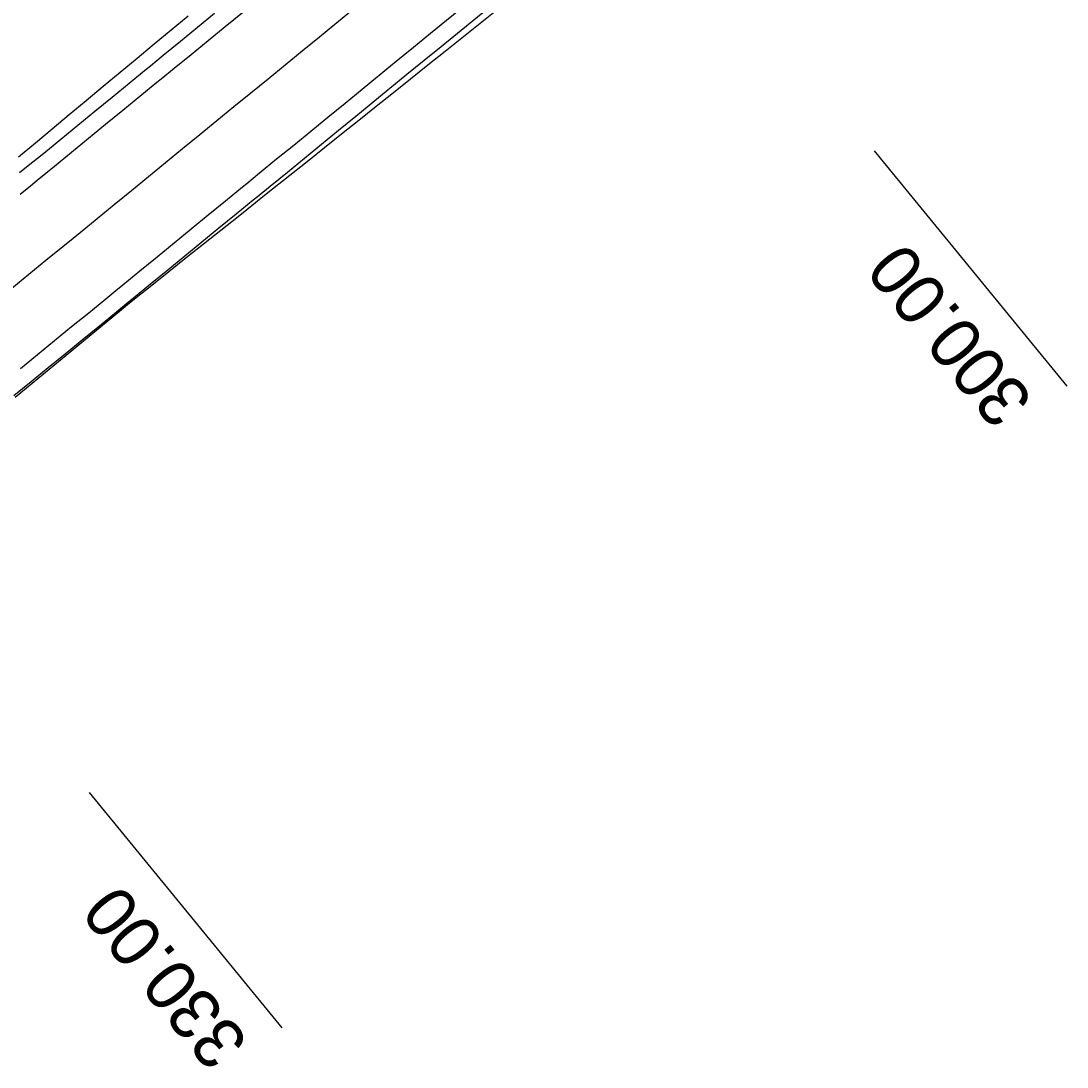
# Model space of a CAD drawing. Extents: x -550605 to -538780, y -1102367 to -1093705.
# Drawn here: x -546744.28 to -546713.33, y -1100829.28 to -1100798.32 of the extents above; entities that cross this region are included whole.
import ezdxf

# ---------------------------------------------------------------- set-up
doc = ezdxf.new("R2010")
doc.units = 0
for name, color, linetype in [('SIT - hrany vozovky', 7, 'Continuous'), ('SIT - osa cesty', 7, 'Continuous'), ('SIT - paty násypů', 7, 'Continuous'), ('SIT - staničení po 30m', 7, 'Continuous')]:
    doc.layers.add(name, color=color, linetype=linetype)

msp = doc.modelspace()

# ---------------------------------------------------------------- linework, layer by layer
at = {"layer": 'SIT - hrany vozovky'}
for points in [[(-546729.855, -1100796.812), (-546732.161, -1100798.697), (-546732.666, -1100799.11), (-546733.172, -1100799.524), (-546733.678, -1100799.937), (-546733.726, -1100799.977), (-546734.183, -1100800.35), (-546734.689, -1100800.764), (-546735.195, -1100801.177), (-546735.7, -1100801.591), (-546736.206, -1100802.004), (-546736.712, -1100802.417), (-546737.217, -1100802.831), (-546737.597, -1100803.141), (-546737.723, -1100803.244), (-546738.228, -1100803.658), (-546738.734, -1100804.071), (-546739.24, -1100804.484), (-546739.745, -1100804.898), (-546740.251, -1100805.311), (-546740.757, -1100805.725), (-546741.262, -1100806.138), (-546741.468, -1100806.306), (-546741.768, -1100806.551), (-546742.274, -1100806.965), (-546742.779, -1100807.378), (-546743.285, -1100807.792), (-546743.79, -1100808.205), (-546744.296, -1100808.618)], [(-546729.539, -1100797.199), (-546731.844, -1100799.084), (-546732.35, -1100799.497), (-546732.856, -1100799.911), (-546733.361, -1100800.324), (-546733.41, -1100800.364), (-546733.867, -1100800.737), (-546734.372, -1100801.151), (-546734.878, -1100801.564), (-546735.384, -1100801.978), (-546735.889, -1100802.391), (-546736.395, -1100802.804), (-546736.901, -1100803.218), (-546737.281, -1100803.528), (-546737.406, -1100803.631), (-546737.912, -1100804.045), (-546738.418, -1100804.458), (-546738.923, -1100804.871), (-546739.429, -1100805.285), (-546739.935, -1100805.698), (-546740.44, -1100806.112), (-546740.946, -1100806.525), (-546741.151, -1100806.693), (-546741.451, -1100806.939), (-546741.957, -1100807.352), (-546742.463, -1100807.765), (-546742.968, -1100808.179), (-546743.474, -1100808.592), (-546743.98, -1100809.006), (-546744.485, -1100809.419)], [(-546738.549, -1100798.107), (-546739.054, -1100798.52), (-546739.56, -1100798.934), (-546740.065, -1100799.347), (-546740.445, -1100799.658), (-546740.571, -1100799.76), (-546741.077, -1100800.174), (-546741.582, -1100800.587), (-546742.088, -1100801.001), (-546742.594, -1100801.414), (-546743.099, -1100801.827), (-546743.605, -1100802.241), (-546744.111, -1100802.654), (-546744.316, -1100802.822)], [(-546737.726, -1100798.08), (-546738.232, -1100798.494), (-546738.738, -1100798.907), (-546739.243, -1100799.321), (-546739.749, -1100799.734), (-546740.129, -1100800.045), (-546740.255, -1100800.147), (-546740.76, -1100800.561), (-546741.266, -1100800.974), (-546741.772, -1100801.388), (-546742.277, -1100801.801), (-546742.783, -1100802.214), (-546743.288, -1100802.628), (-546743.794, -1100803.041), (-546744, -1100803.209), (-546744.3, -1100803.455)]]:
    msp.add_lwpolyline(points, dxfattribs=at)
at = {"layer": 'SIT - osa cesty'}
msp.add_lwpolyline([(-546734.438, -1100797.975), (-546734.944, -1100798.389), (-546734.992, -1100798.428), (-546735.449, -1100798.802), (-546735.955, -1100799.215), (-546736.461, -1100799.629), (-546736.966, -1100800.042), (-546737.472, -1100800.456), (-546737.977, -1100800.869), (-546738.483, -1100801.282), (-546738.863, -1100801.593), (-546738.989, -1100801.696), (-546739.494, -1100802.109), (-546740, -1100802.523), (-546740.506, -1100802.936), (-546741.011, -1100803.349), (-546741.517, -1100803.763), (-546742.023, -1100804.176), (-546742.528, -1100804.59), (-546742.734, -1100804.758), (-546743.034, -1100805.003), (-546743.539, -1100805.416), (-546744.045, -1100805.83), (-546744.551, -1100806.243)], dxfattribs=at)
at = {"layer": 'SIT - paty násypů'}
for points in [[(-546729.407, -1100797.36), (-546731.73, -1100799.224), (-546732.239, -1100799.633), (-546732.749, -1100800.041), (-546733.259, -1100800.45), (-546733.307, -1100800.489), (-546733.769, -1100800.858), (-546734.279, -1100801.266), (-546734.789, -1100801.673), (-546735.299, -1100802.081), (-546735.81, -1100802.489), (-546736.32, -1100802.896), (-546736.831, -1100803.303), (-546737.215, -1100803.609), (-546737.342, -1100803.71), (-546737.853, -1100804.117), (-546738.364, -1100804.524), (-546738.875, -1100804.93), (-546739.386, -1100805.337), (-546739.898, -1100805.743), (-546740.41, -1100806.149), (-546740.921, -1100806.555), (-546741.128, -1100806.722), (-546741.426, -1100806.97), (-546741.929, -1100807.386), (-546742.432, -1100807.802), (-546742.936, -1100808.218), (-546743.439, -1100808.634), (-546743.943, -1100809.05), (-546744.447, -1100809.466)], [(-546739.333, -1100798.18), (-546739.835, -1100798.597), (-546740.338, -1100799.014), (-546740.715, -1100799.328), (-546740.84, -1100799.431), (-546741.342, -1100799.849), (-546741.844, -1100800.267), (-546742.346, -1100800.685), (-546742.848, -1100801.103), (-546743.35, -1100801.521), (-546743.851, -1100801.94), (-546744.353, -1100802.358)]]:
    msp.add_lwpolyline(points, dxfattribs=at)
at = {"layer": 'SIT - staničení po 30m'}
for points in [[(-546713.325, -1100809.131), (-546719.022, -1100802.163)], [(-546736.551, -1100828.119), (-546742.247, -1100821.152)]]:
    msp.add_lwpolyline(points, dxfattribs=at)

# ---------------------------------------------------------------- texts
for s, p in [('300.00', (-546714.282, -1100809.54)), ('330.00', (-546737.5, -1100828.538))]:
    msp.add_text(s, height=1.5, rotation=129.269, dxfattribs=at).set_placement(p)

doc.saveas('drawing.dxf')
